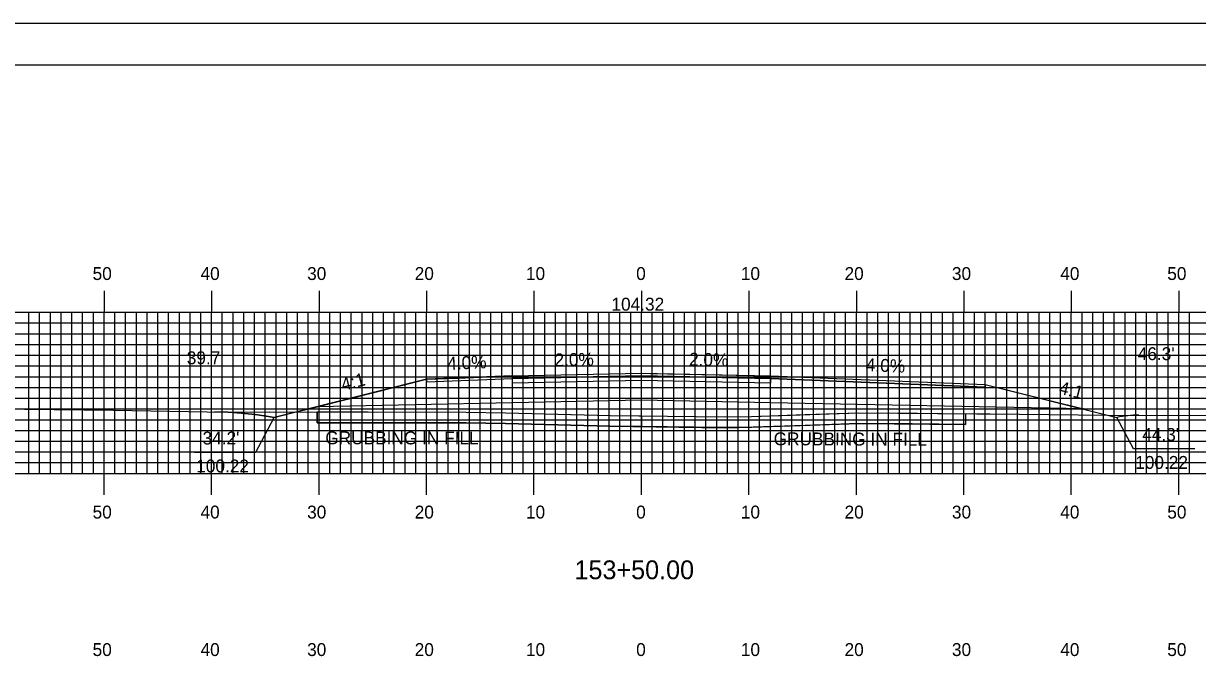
# Model space of a CAD drawing. Extents: x 1778712 to 1779055, y 442591 to 442811.
# Drawn here: x 1778820.3 to 1778929.6, y 442751.2 to 442810.5 of the extents above; entities that cross this region are included whole.
import ezdxf

# ---------------------------------------------------------------- set-up
doc = ezdxf.new("R2010")
doc.units = 0
for name, color, linetype in [('ANNOTATION', 7, 'Continuous'), ('BORDER', 7, 'Continuous'), ('D_Roadway_Centerline', 7, 'Continuous'), ('D_Roadway_Centerline_Text', 7, 'Continuous'), ('D_Roadway_Edge_Shoulder', 7, 'Continuous'), ('D_Roadway_Edge_TW', 7, 'Continuous'), ('D_Roadway_Pavement', 7, 'Continuous'), ('D_Roadway_SlopeLines', 7, 'Continuous'), ('D_Roadway_SubGrade', 7, 'Continuous'), ('D_Text_Standard', 7, 'Continuous'), ('GRUBBING IN FILL', 7, 'Continuous'), ('H_V ANNOTATION', 7, 'Continuous'), ('MAJOR', 7, 'Continuous'), ('MINOR', 7, 'Continuous'), ('PLOT BOUNDARY', 7, 'Continuous'), ('S_Roadway_Centerline', 7, 'Continuous')]:
    doc.layers.add(name, color=color, linetype=linetype)

msp = doc.modelspace()

# ---------------------------------------------------------------- linework, layer by layer
at = {"layer": 'ANNOTATION'}
for points in [[(1778836.24, 442770.63), (1778841.93, 442770.63), (1778843.64, 442773.88)], [(1778929.31, 442770.96), (1778923.62, 442770.96), (1778922.07, 442773.88)]]:
    msp.add_lwpolyline(points, dxfattribs=at)
at = {"layer": 'BORDER'}
msp.add_lwpolyline([(1778728.22, 442596.67), (1779048.22, 442596.67), (1779048.22, 442806.67), (1778728.22, 442806.67)], close=True, dxfattribs=at)
at = {"layer": 'D_Roadway_Centerline'}
msp.add_lwpolyline([(1778838.11, 442774.4), (1778838.13, 442774.4), (1778839.36, 442774.37), (1778840.19, 442774.32), (1778840.61, 442774.29), (1778841.23, 442774.22), (1778841.86, 442774.16), (1778843.11, 442773.97), (1778843.64, 442773.88), (1778845.2, 442774.27), (1778847.64, 442774.88), (1778857.82, 442777.43), (1778860.73, 442777.54), (1778865.82, 442777.75), (1778877.82, 442777.99), (1778878.65, 442777.97), (1778889.82, 442777.75), (1778909.82, 442776.95), (1778918.94, 442774.67)], dxfattribs=at)
at = {"layer": 'D_Roadway_Edge_Shoulder'}
for points in [[(1778865.82, 442777.75), (1778857.82, 442777.43), (1778857.82, 442777.18), (1778865.82, 442777.5)], [(1778889.82, 442777.75), (1778909.82, 442776.95), (1778909.82, 442776.7), (1778889.82, 442777.5)]]:
    msp.add_lwpolyline(points, close=True, dxfattribs=at)
at = {"layer": 'D_Roadway_Edge_TW'}
msp.add_lwpolyline([(1778865.82, 442777.5), (1778865.82, 442777.75), (1778877.82, 442777.99), (1778889.82, 442777.75), (1778889.82, 442777.5), (1778877.82, 442777.74)], close=True, dxfattribs=at)
at = {"layer": 'D_Roadway_Pavement'}
msp.add_lwpolyline([(1778865.82, 442777.08), (1778865.82, 442777.5), (1778877.82, 442777.74), (1778889.82, 442777.5), (1778889.82, 442777.08), (1778877.82, 442777.32)], close=True, dxfattribs=at)
at = {"layer": 'D_Roadway_SlopeLines'}
for points in [[(1778857.82, 442777.43), (1778843.64, 442773.88)], [(1778909.82, 442776.95), (1778922.07, 442773.88)], [(1778843.64, 442773.88), (1778843.11, 442773.97), (1778841.86, 442774.16), (1778840.61, 442774.29), (1778839.36, 442774.37), (1778838.11, 442774.4)]]:
    msp.add_lwpolyline(points, dxfattribs=at)
msp.add_arc((1778924.07, 442764.09), 10, 89.7285, 101.5799, dxfattribs=at)
at = {"layer": 'D_Roadway_SubGrade'}
msp.add_lwpolyline([(1778865.82, 442775.25), (1778847.64, 442774.88), (1778857.82, 442777.43), (1778857.82, 442777.18), (1778865.82, 442777.5), (1778877.82, 442777.74), (1778889.82, 442777.5), (1778909.82, 442776.7), (1778909.82, 442776.95), (1778918.94, 442774.67), (1778889.82, 442775.25), (1778877.82, 442775.49)], close=True, dxfattribs=at)
at = {"layer": 'GRUBBING IN FILL'}
for p, q in [((1778847.64, 442774.39), (1778847.64, 442773.39)), ((1778847.64, 442774.39), (1778847.64, 442773.39)), ((1778907.99, 442774.22), (1778907.99, 442773.22)), ((1778907.99, 442774.22), (1778907.99, 442773.22))]:
    msp.add_line(p, q, dxfattribs=at)
for points in [[(1778847.64, 442774.39), (1778852.38, 442774.39), (1778861.52, 442774.38), (1778865.21, 442774.3), (1778870.05, 442774.18), (1778874.9, 442774.06), (1778877.82, 442774.02), (1778877.82, 442773.02), (1778874.88, 442773.06), (1778870.03, 442773.18), (1778865.18, 442773.3), (1778861.5, 442773.38), (1778854.57, 442773.39), (1778847.64, 442773.39)], [(1778847.64, 442774.39), (1778852.38, 442774.39), (1778861.52, 442774.38), (1778865.21, 442774.3), (1778870.05, 442774.18), (1778874.9, 442774.06), (1778877.82, 442774.02), (1778877.82, 442773.02), (1778874.88, 442773.06), (1778870.03, 442773.18), (1778865.18, 442773.3), (1778861.5, 442773.38), (1778854.57, 442773.39), (1778847.64, 442773.39)], [(1778877.82, 442774.02), (1778880.23, 442773.99), (1778885.57, 442773.92), (1778888.07, 442773.97), (1778893.04, 442774.14), (1778898.01, 442774.31), (1778903.52, 442774.26), (1778907.99, 442774.22), (1778907.99, 442773.22), (1778903.01, 442773.27), (1778898.03, 442773.31), (1778893.06, 442773.14), (1778888.23, 442772.97), (1778886.83, 442772.95), (1778885.1, 442772.93), (1778880.22, 442772.99), (1778877.82, 442773.02)], [(1778877.82, 442774.02), (1778880.23, 442773.99), (1778885.57, 442773.92), (1778888.07, 442773.97), (1778893.04, 442774.14), (1778898.01, 442774.31), (1778903.52, 442774.26), (1778907.99, 442774.22), (1778907.99, 442773.22), (1778903.01, 442773.27), (1778898.03, 442773.31), (1778893.06, 442773.14), (1778888.23, 442772.97), (1778886.83, 442772.95), (1778885.1, 442772.93), (1778880.22, 442772.99), (1778877.82, 442773.02)]]:
    msp.add_lwpolyline(points, close=True, dxfattribs=at)
msp.add_lwpolyline([(1778847.64, 442773.39), (1778861.5, 442773.38), (1778865.18, 442773.3), (1778874.88, 442773.06), (1778885.57, 442772.92), (1778888.09, 442772.97), (1778898.03, 442773.31), (1778907.99, 442773.22)], dxfattribs=at)
msp.add_lwpolyline([(1778847.64, 442773.39), (1778861.5, 442773.38), (1778865.18, 442773.3), (1778874.88, 442773.06), (1778885.57, 442772.92), (1778888.09, 442772.97), (1778898.03, 442773.31), (1778907.99, 442773.22)], dxfattribs=at)
at = {"layer": 'MAJOR'}
for p, q in [((1778827.82, 442785.67), (1778827.82, 442783.67)), ((1778837.82, 442785.67), (1778837.82, 442783.67)), ((1778847.82, 442785.67), (1778847.82, 442783.67)), ((1778857.82, 442785.67), (1778857.82, 442783.67)), ((1778867.82, 442785.67), (1778867.82, 442783.67)), ((1778877.82, 442785.67), (1778877.82, 442783.67)), ((1778887.82, 442785.67), (1778887.82, 442783.67)), ((1778897.82, 442785.67), (1778897.82, 442783.67)), ((1778907.82, 442785.67), (1778907.82, 442783.67)), ((1778917.82, 442785.67), (1778917.82, 442783.67)), ((1778927.82, 442785.67), (1778927.82, 442783.67)), ((1778737.82, 442783.67), (1779017.82, 442783.67)), ((1778737.82, 442783.67), (1779017.82, 442783.67)), ((1778827.82, 442768.67), (1778827.82, 442783.67)), ((1778837.82, 442768.67), (1778837.82, 442783.67)), ((1778847.82, 442768.67), (1778847.82, 442783.67)), ((1778857.82, 442768.67), (1778857.82, 442783.67)), ((1778867.82, 442768.67), (1778867.82, 442783.67)), ((1778877.82, 442768.67), (1778877.82, 442783.67)), ((1778887.82, 442768.67), (1778887.82, 442783.67)), ((1778897.82, 442768.67), (1778897.82, 442783.67)), ((1778907.82, 442768.67), (1778907.82, 442783.67)), ((1778917.82, 442768.67), (1778917.82, 442783.67)), ((1778927.82, 442768.67), (1778927.82, 442783.67)), ((1778737.82, 442778.67), (1779017.82, 442778.67)), ((1778737.82, 442773.67), (1779017.82, 442773.67)), ((1778737.82, 442768.67), (1779017.82, 442768.67)), ((1778737.82, 442768.67), (1779017.82, 442768.67)), ((1778827.82, 442766.66), (1778827.82, 442768.67)), ((1778837.82, 442766.66), (1778837.82, 442768.67)), ((1778847.82, 442766.66), (1778847.82, 442768.67)), ((1778857.82, 442766.66), (1778857.82, 442768.67)), ((1778867.82, 442766.66), (1778867.82, 442768.67)), ((1778877.82, 442766.66), (1778877.82, 442768.67)), ((1778887.82, 442766.66), (1778887.82, 442768.67)), ((1778897.82, 442766.66), (1778897.82, 442768.67)), ((1778907.82, 442766.66), (1778907.82, 442768.67)), ((1778917.82, 442766.66), (1778917.82, 442768.67)), ((1778927.82, 442766.66), (1778927.82, 442768.67))]:
    msp.add_line(p, q, dxfattribs=at)
at = {"layer": 'MINOR'}
for p, q in [((1778820.82, 442768.67), (1778820.82, 442783.67)), ((1778821.82, 442768.67), (1778821.82, 442783.67)), ((1778822.82, 442768.67), (1778822.82, 442783.67)), ((1778823.82, 442768.67), (1778823.82, 442783.67)), ((1778824.82, 442768.67), (1778824.82, 442783.67)), ((1778825.82, 442768.67), (1778825.82, 442783.67)), ((1778826.82, 442768.67), (1778826.82, 442783.67)), ((1778828.82, 442768.67), (1778828.82, 442783.67)), ((1778829.82, 442768.67), (1778829.82, 442783.67)), ((1778830.82, 442768.67), (1778830.82, 442783.67)), ((1778831.82, 442768.67), (1778831.82, 442783.67)), ((1778832.82, 442768.67), (1778832.82, 442783.67)), ((1778833.82, 442768.67), (1778833.82, 442783.67)), ((1778834.82, 442768.67), (1778834.82, 442783.67)), ((1778835.82, 442768.67), (1778835.82, 442783.67)), ((1778836.82, 442768.67), (1778836.82, 442783.67)), ((1778838.82, 442768.67), (1778838.82, 442783.67)), ((1778839.82, 442768.67), (1778839.82, 442783.67)), ((1778840.82, 442768.67), (1778840.82, 442783.67)), ((1778841.82, 442768.67), (1778841.82, 442783.67)), ((1778842.82, 442768.67), (1778842.82, 442783.67)), ((1778843.82, 442768.67), (1778843.82, 442783.67)), ((1778844.82, 442768.67), (1778844.82, 442783.67)), ((1778845.82, 442768.67), (1778845.82, 442783.67)), ((1778846.82, 442768.67), (1778846.82, 442783.67)), ((1778848.82, 442768.67), (1778848.82, 442783.67)), ((1778849.82, 442768.67), (1778849.82, 442783.67)), ((1778850.82, 442768.67), (1778850.82, 442783.67)), ((1778851.82, 442768.67), (1778851.82, 442783.67)), ((1778852.82, 442768.67), (1778852.82, 442783.67)), ((1778853.82, 442768.67), (1778853.82, 442783.67)), ((1778854.82, 442768.67), (1778854.82, 442783.67)), ((1778855.82, 442768.67), (1778855.82, 442783.67)), ((1778856.82, 442768.67), (1778856.82, 442783.67)), ((1778858.82, 442768.67), (1778858.82, 442783.67)), ((1778859.82, 442768.67), (1778859.82, 442783.67)), ((1778860.82, 442768.67), (1778860.82, 442783.67)), ((1778861.82, 442768.67), (1778861.82, 442783.67)), ((1778862.82, 442768.67), (1778862.82, 442783.67)), ((1778863.82, 442768.67), (1778863.82, 442783.67)), ((1778864.82, 442768.67), (1778864.82, 442783.67)), ((1778865.82, 442768.67), (1778865.82, 442783.67)), ((1778866.82, 442768.67), (1778866.82, 442783.67)), ((1778868.82, 442768.67), (1778868.82, 442783.67)), ((1778869.82, 442768.67), (1778869.82, 442783.67)), ((1778870.82, 442768.67), (1778870.82, 442783.67)), ((1778871.82, 442768.67), (1778871.82, 442783.67)), ((1778872.82, 442768.67), (1778872.82, 442783.67)), ((1778873.82, 442768.67), (1778873.82, 442783.67)), ((1778874.82, 442768.67), (1778874.82, 442783.67)), ((1778875.82, 442768.67), (1778875.82, 442783.67)), ((1778876.82, 442768.67), (1778876.82, 442783.67)), ((1778878.82, 442768.67), (1778878.82, 442783.67)), ((1778879.82, 442768.67), (1778879.82, 442783.67)), ((1778880.82, 442768.67), (1778880.82, 442783.67)), ((1778881.82, 442768.67), (1778881.82, 442783.67)), ((1778882.82, 442768.67), (1778882.82, 442783.67)), ((1778883.82, 442768.67), (1778883.82, 442783.67)), ((1778884.82, 442768.67), (1778884.82, 442783.67)), ((1778885.82, 442768.67), (1778885.82, 442783.67)), ((1778886.82, 442768.67), (1778886.82, 442783.67)), ((1778888.82, 442768.67), (1778888.82, 442783.67)), ((1778889.82, 442768.67), (1778889.82, 442783.67)), ((1778890.82, 442768.67), (1778890.82, 442783.67)), ((1778891.82, 442768.67), (1778891.82, 442783.67)), ((1778892.82, 442768.67), (1778892.82, 442783.67)), ((1778893.82, 442768.67), (1778893.82, 442783.67)), ((1778894.82, 442768.67), (1778894.82, 442783.67)), ((1778895.82, 442768.67), (1778895.82, 442783.67)), ((1778896.82, 442768.67), (1778896.82, 442783.67)), ((1778898.82, 442768.67), (1778898.82, 442783.67)), ((1778899.82, 442768.67), (1778899.82, 442783.67)), ((1778900.82, 442768.67), (1778900.82, 442783.67)), ((1778901.82, 442768.67), (1778901.82, 442783.67)), ((1778902.82, 442768.67), (1778902.82, 442783.67)), ((1778903.82, 442768.67), (1778903.82, 442783.67)), ((1778904.82, 442768.67), (1778904.82, 442783.67)), ((1778905.82, 442768.67), (1778905.82, 442783.67)), ((1778906.82, 442768.67), (1778906.82, 442783.67)), ((1778908.82, 442768.67), (1778908.82, 442783.67)), ((1778909.82, 442768.67), (1778909.82, 442783.67)), ((1778910.82, 442768.67), (1778910.82, 442783.67)), ((1778911.82, 442768.67), (1778911.82, 442783.67)), ((1778912.82, 442768.67), (1778912.82, 442783.67)), ((1778913.82, 442768.67), (1778913.82, 442783.67)), ((1778914.82, 442768.67), (1778914.82, 442783.67)), ((1778915.82, 442768.67), (1778915.82, 442783.67)), ((1778916.82, 442768.67), (1778916.82, 442783.67)), ((1778918.82, 442768.67), (1778918.82, 442783.67)), ((1778919.82, 442768.67), (1778919.82, 442783.67)), ((1778920.82, 442768.67), (1778920.82, 442783.67)), ((1778921.82, 442768.67), (1778921.82, 442783.67)), ((1778922.82, 442768.67), (1778922.82, 442783.67)), ((1778923.82, 442768.67), (1778923.82, 442783.67)), ((1778924.82, 442768.67), (1778924.82, 442783.67)), ((1778925.82, 442768.67), (1778925.82, 442783.67)), ((1778926.82, 442768.67), (1778926.82, 442783.67)), ((1778928.82, 442768.67), (1778928.82, 442783.67)), ((1778737.82, 442782.67), (1779017.82, 442782.67)), ((1778737.82, 442781.67), (1779017.82, 442781.67)), ((1778737.82, 442780.67), (1779017.82, 442780.67)), ((1778737.82, 442779.67), (1779017.82, 442779.67)), ((1778737.82, 442777.67), (1779017.82, 442777.67)), ((1778737.82, 442776.67), (1779017.82, 442776.67)), ((1778737.82, 442775.67), (1779017.82, 442775.67)), ((1778737.82, 442774.67), (1779017.82, 442774.67)), ((1778737.82, 442772.67), (1779017.82, 442772.67)), ((1778737.82, 442771.67), (1779017.82, 442771.67)), ((1778737.82, 442770.67), (1779017.82, 442770.67)), ((1778737.82, 442769.67), (1779017.82, 442769.67))]:
    msp.add_line(p, q, dxfattribs=at)
at = {"layer": 'PLOT BOUNDARY'}
msp.add_lwpolyline([(1778712.03, 442590.55), (1779052.03, 442590.55), (1779052.03, 442810.55), (1778712.03, 442810.55)], close=True, dxfattribs=at)
at = {"layer": 'S_Roadway_Centerline'}
msp.add_lwpolyline([(1778817.64, 442774.69), (1778820.42, 442774.66), (1778828.7, 442774.54), (1778839.15, 442774.38), (1778843.25, 442774.4), (1778861.52, 442774.38), (1778865.21, 442774.3), (1778874.9, 442774.06), (1778885.57, 442773.92), (1778888.07, 442773.97), (1778898.01, 442774.31), (1778909.03, 442774.21), (1778909.66, 442774.2), (1778910.26, 442774.2), (1778921.19, 442774.1), (1778932.72, 442774.05)], dxfattribs=at)

# ---------------------------------------------------------------- texts
at = {"layer": 'ANNOTATION'}
for s, rotation, p in [('2.0%', 1.1458, (1778869.74, 442778.63)), ('2.0%', 358.8542, (1778882.24, 442778.7)), ('4.0%', 2.2907, (1778859.77, 442778.31)), ('4.0%', 357.7095, (1778898.68, 442778.19)), ('4:1', 14.0337, (1778850.05, 442776.35)), ('4:1', 345.9649, (1778916.59, 442776.11))]:
    msp.add_text(s, height=1.2, rotation=rotation, dxfattribs=at).set_placement(p)
for s, p in [("34.2'", (1778836.98, 442771.36)), ("44.3'", (1778924.42, 442771.69)), ('100.22', (1778836.39, 442768.76)), ('100.22', (1778923.77, 442769.09))]:
    msp.add_text(s, height=1.2, dxfattribs=at).set_placement(p)
at = {"layer": 'D_Roadway_Centerline'}
for s, p in [('C', (1778877.81, 442777.99)), ('L', (1778877.82, 442777.98))]:
    msp.add_text(s, height=0.0146, dxfattribs=at).set_placement(p)
at = {"layer": 'D_Roadway_Centerline_Text'}
msp.add_text('104.32', height=1.2, dxfattribs=at).set_placement((1778875.03, 442783.82))
at = {"layer": 'D_Text_Standard'}
for s, p in [("39.7'", (1778835.51, 442778.83)), ("46.3'", (1778924, 442779.21))]:
    msp.add_text(s, height=1.2, dxfattribs=at).set_placement(p)
at = {"layer": 'GRUBBING IN FILL'}
for rotation, p in [(359.9351, (1778848.4, 442771.38)), (359.8053, (1778890.12, 442771.29))]:
    msp.add_text('GRUBBING IN FILL', height=1.2, rotation=rotation, dxfattribs=at).set_placement(p)
at = {"layer": 'H_V ANNOTATION'}
for s, height, p in [('50', 1.2, (1778826.75, 442786.67)), ('40', 1.2, (1778836.79, 442786.67)), ('30', 1.2, (1778846.71, 442786.67)), ('20', 1.2, (1778856.72, 442786.67)), ('10', 1.2, (1778867.07, 442786.67)), ('0', 1.2, (1778877.33, 442786.67)), ('10', 1.2, (1778887.07, 442786.67)), ('20', 1.2, (1778896.72, 442786.67)), ('30', 1.2, (1778906.71, 442786.67)), ('40', 1.2, (1778916.79, 442786.67)), ('50', 1.2, (1778926.75, 442786.67)), ('50', 1.2, (1778826.75, 442764.47)), ('40', 1.2, (1778836.79, 442764.47)), ('30', 1.2, (1778846.71, 442764.47)), ('20', 1.2, (1778856.72, 442764.47)), ('10', 1.2, (1778867.07, 442764.47)), ('0', 1.2, (1778877.33, 442764.47)), ('10', 1.2, (1778887.07, 442764.47)), ('20', 1.2, (1778896.72, 442764.47)), ('30', 1.2, (1778906.71, 442764.47)), ('40', 1.2, (1778916.79, 442764.47)), ('50', 1.2, (1778926.75, 442764.47)), ('153+50.00', 1.75, (1778871.59, 442758.82)), ('50', 1.2, (1778826.75, 442751.67)), ('40', 1.2, (1778836.79, 442751.67)), ('30', 1.2, (1778846.71, 442751.67)), ('20', 1.2, (1778856.72, 442751.67)), ('10', 1.2, (1778867.07, 442751.67)), ('0', 1.2, (1778877.33, 442751.67)), ('10', 1.2, (1778887.07, 442751.67)), ('20', 1.2, (1778896.72, 442751.67)), ('30', 1.2, (1778906.71, 442751.67)), ('40', 1.2, (1778916.79, 442751.67)), ('50', 1.2, (1778926.75, 442751.67))]:
    msp.add_text(s, height=height, dxfattribs=at).set_placement(p)

doc.saveas('drawing.dxf')
